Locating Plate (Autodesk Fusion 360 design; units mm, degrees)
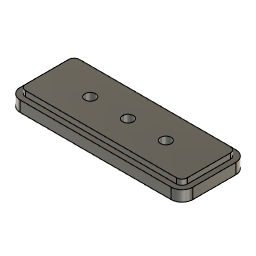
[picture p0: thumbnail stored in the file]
sketch "Sketch1" plane through (0, 0, 0) normal (0, 0, 1) x axis (1, 0, 0)
  line L1 (-50.8, -19.05) -> (50.8, -19.05)
  line L2 (-50.8, 19.05) -> (-50.8, -19.05)
  line L3 (50.8, 19.05) -> (-50.8, 19.05)
  line L4 (50.8, -19.05) -> (50.8, 19.05)
  line L5 (-50.8, 19.05) -> (50.8, -19.05)
  line L6 (50.8, 19.05) -> (-50.8, -19.05)
  point P6 (0, 0)
  point P1 (0, 0)
  point P4 (-50.8, 19.05)
  point P5 (50.8, 19.05)
  point P3 (-50.8, -19.05)
  point P2 (50.8, -19.05)
  perpendicular L1 L2
  parallel L1 L3
  parallel L2 L4
  horizontal L1
  coincident L5 P6
  coincident L6 P6
  coincident P1 P6
  dimension "d1" distance P4 P5 = 101.6
  dimension "d2" distance P3 P4 = 38.1
  dimension "d9" distance P2 = 25.4
extrude "Extrude1" new body sketch "Sketch1" profile of L1 L2 L3 L4 along normal blind 6.35
fillet "Fillet1" radius 6.35
sketch "Sketch2" plane through (0, 0, 6.35) normal (0, 0, 1) x axis (-1, 0, 0)
  line L1 (-50.8, -12.7) -> (-50.8, 12.7)
  line L2 (44.45, -19.05) -> (-44.45, -19.05)
  line L3 (50.8, 12.7) -> (50.8, -12.7)
  line L4 (-44.45, 19.05) -> (44.45, 19.05)
  line L5 (47.625, 12.7) -> (47.625, -12.7)
  line L6 (-44.45, 15.875) -> (44.45, 15.875)
  line L7 (-47.625, -12.7) -> (-47.625, 12.7)
  line L8 (44.45, -15.875) -> (-44.45, -15.875)
  arc A1 centre (-44.45, 12.7) radius 6.35 clockwise from (-50.8, 12.7) to (-44.45, 19.05)
  arc A2 centre (-44.45, -12.7) radius 6.35 clockwise from (-44.45, -19.05) to (-50.8, -12.7)
  arc A3 centre (44.45, -12.7) radius 6.35 clockwise from (50.8, -12.7) to (44.45, -19.05)
  arc A4 centre (44.45, 12.7) radius 6.35 clockwise from (44.45, 19.05) to (50.8, 12.7)
  arc A5 centre (44.45, 12.7) radius 3.175 clockwise from (44.45, 15.875) to (47.625, 12.7)
  arc A6 centre (-44.45, 12.7) radius 3.175 clockwise from (-47.625, 12.7) to (-44.45, 15.875)
  arc A7 centre (-44.45, -12.7) radius 3.175 clockwise from (-44.45, -15.875) to (-47.625, -12.7)
  arc A8 centre (44.45, -12.7) radius 3.175 clockwise from (47.625, -12.7) to (44.45, -15.875)
  dimension "d6" = -3.175
extrude "Extrude2" add sketch "Sketch2" profile of L5 A5 A6 L6 A7 L7 A8 L8 along normal blind 3.175
sketch "Sketch3" plane through (0, 0, 9.525) normal (0, 0, 1) x axis (-1, 0, 0)
  line L1 (47.625, 12.7) -> (47.625, -12.7)
  line L2 (-44.45, 15.875) -> (44.45, 15.875)
  line L3 (-47.625, -12.7) -> (-47.625, 12.7)
  line L4 (44.45, -15.875) -> (-44.45, -15.875)
  line L5 (22.225, 0) -> (47.625, 0)
  line L6 (-22.225, 0) -> (22.225, 0)
  line L7 (-47.625, 0) -> (-22.225, 0)
  arc A1 centre (44.45, -12.7) radius 3.175 clockwise from (47.625, -12.7) to (44.45, -15.875)
  arc A2 centre (44.45, 12.7) radius 3.175 clockwise from (44.45, 15.875) to (47.625, 12.7)
  arc A3 centre (-44.45, 12.7) radius 3.175 clockwise from (-47.625, 12.7) to (-44.45, 15.875)
  arc A4 centre (-44.45, -12.7) radius 3.175 clockwise from (-44.45, -15.875) to (-47.625, -12.7)
  point P14 (47.625, 0)
  point P17 (-47.625, 0)
  point P15 (22.225, 0)
  point P18 (22.225, 0)
  point P1 (0, 0)
  point P19 (0, 0)
  point P16 (-22.225, 0)
  point P20 (-22.225, 0)
  midpoint L1 P14
  perpendicular L1 L5
  perpendicular L1 L6
  midpoint L3 P17
  perpendicular L3 L7
  equal L5 L7
  coincident P15 P18
  coincident P1 P19
  coincident P16 P20
  dimension "d9" distance P14 P15 = 25.4
hole "Hole1" HoleDepth 9.525 HoleDiameter 6.35 TipAngle 118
